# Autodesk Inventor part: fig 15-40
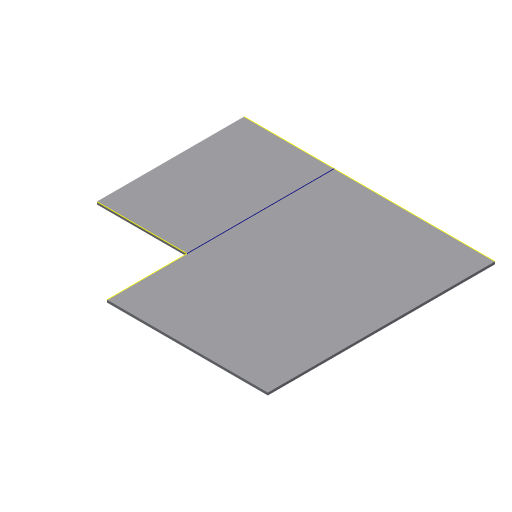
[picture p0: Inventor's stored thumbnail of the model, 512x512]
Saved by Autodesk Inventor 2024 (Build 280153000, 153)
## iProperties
Created: 2005-03
Part Number: fig 15-40
Document SubType Name: Sheet Metal
Designer: CADCIM
Manufacturer: Standard
Standards Organization: Custom
Density: 1 g/cm^3
Sheet Metal Rule: Default
Material: Generic
Appearance: Default
Author: CADCIM
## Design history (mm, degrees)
node "Face1"
  sketch "Sketch1"
    geometry: L1 (31.393, 35.714)-(-19.875, 35.714); L2 (-19.875, 35.714)-(-19.875, 5.625); L3 (-19.875, 5.625)-(-1.5, 5.625); L4 (-1.5, 5.625)-(-1.5, -10.705); L5 (-1.5, -10.705)-(31.393, -10.705); L6 (31.393, -10.705)-(31.393, 35.714)
    constraints: 12 end point, 4 parallel, 1 horizontal, 1 perpendicular
body "Solid1"
sketch "Sketch3"
  geometry: L1 (18.375, -30.089)-(18.375, 0); L2 (18.375, -46.42)-(18.375, -30.089) reference; L3 (18.375, -30.089)-(0, -30.089) reference; L4 (0, 0)-(51.268, 0) reference
  constraints: 3 point on line, 2 end point, 1 vertical
face "Plate1" dims "d1" = 0.5 (= Thickness)
other parameters: "Thickness" = 0.5, "BendRadius" = 0.5 (= Thickness), "BendReliefWidth" = 0.5 (= Thickness), "BendReliefDepth" = 0.25 (= 0.5 x Thickness), "CornerReliefSize" = 2 (= 4 x Thickness), "SeamGap" = 0.01, "MinimumRemnant" = 1 (= 2 x Thickness), "TransitionRadius" = 0.5 (= BendRadius), "d0" = 0.5 (= BendRadius), "JacobiRadiusSize" = 0.5 (= Thickness), "GapSize" = 0.5 (= Thickness)
